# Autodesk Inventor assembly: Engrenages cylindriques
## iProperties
Created: 2011-10
Part Number: Engrenages cylindriques
Document SubType Name: Assembly
Designer: Laur
ClientObjectVersion: 1
Author: Laur
